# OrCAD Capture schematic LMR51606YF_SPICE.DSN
size D; title: LMR51606YF SIMPLE SWITCHERï¿½ 4.5-V to 65-V, 600-mA; note: Datasheet: SLUSEY1     EVM: SLUUCP7; note: Synchronous Step-Down Converter
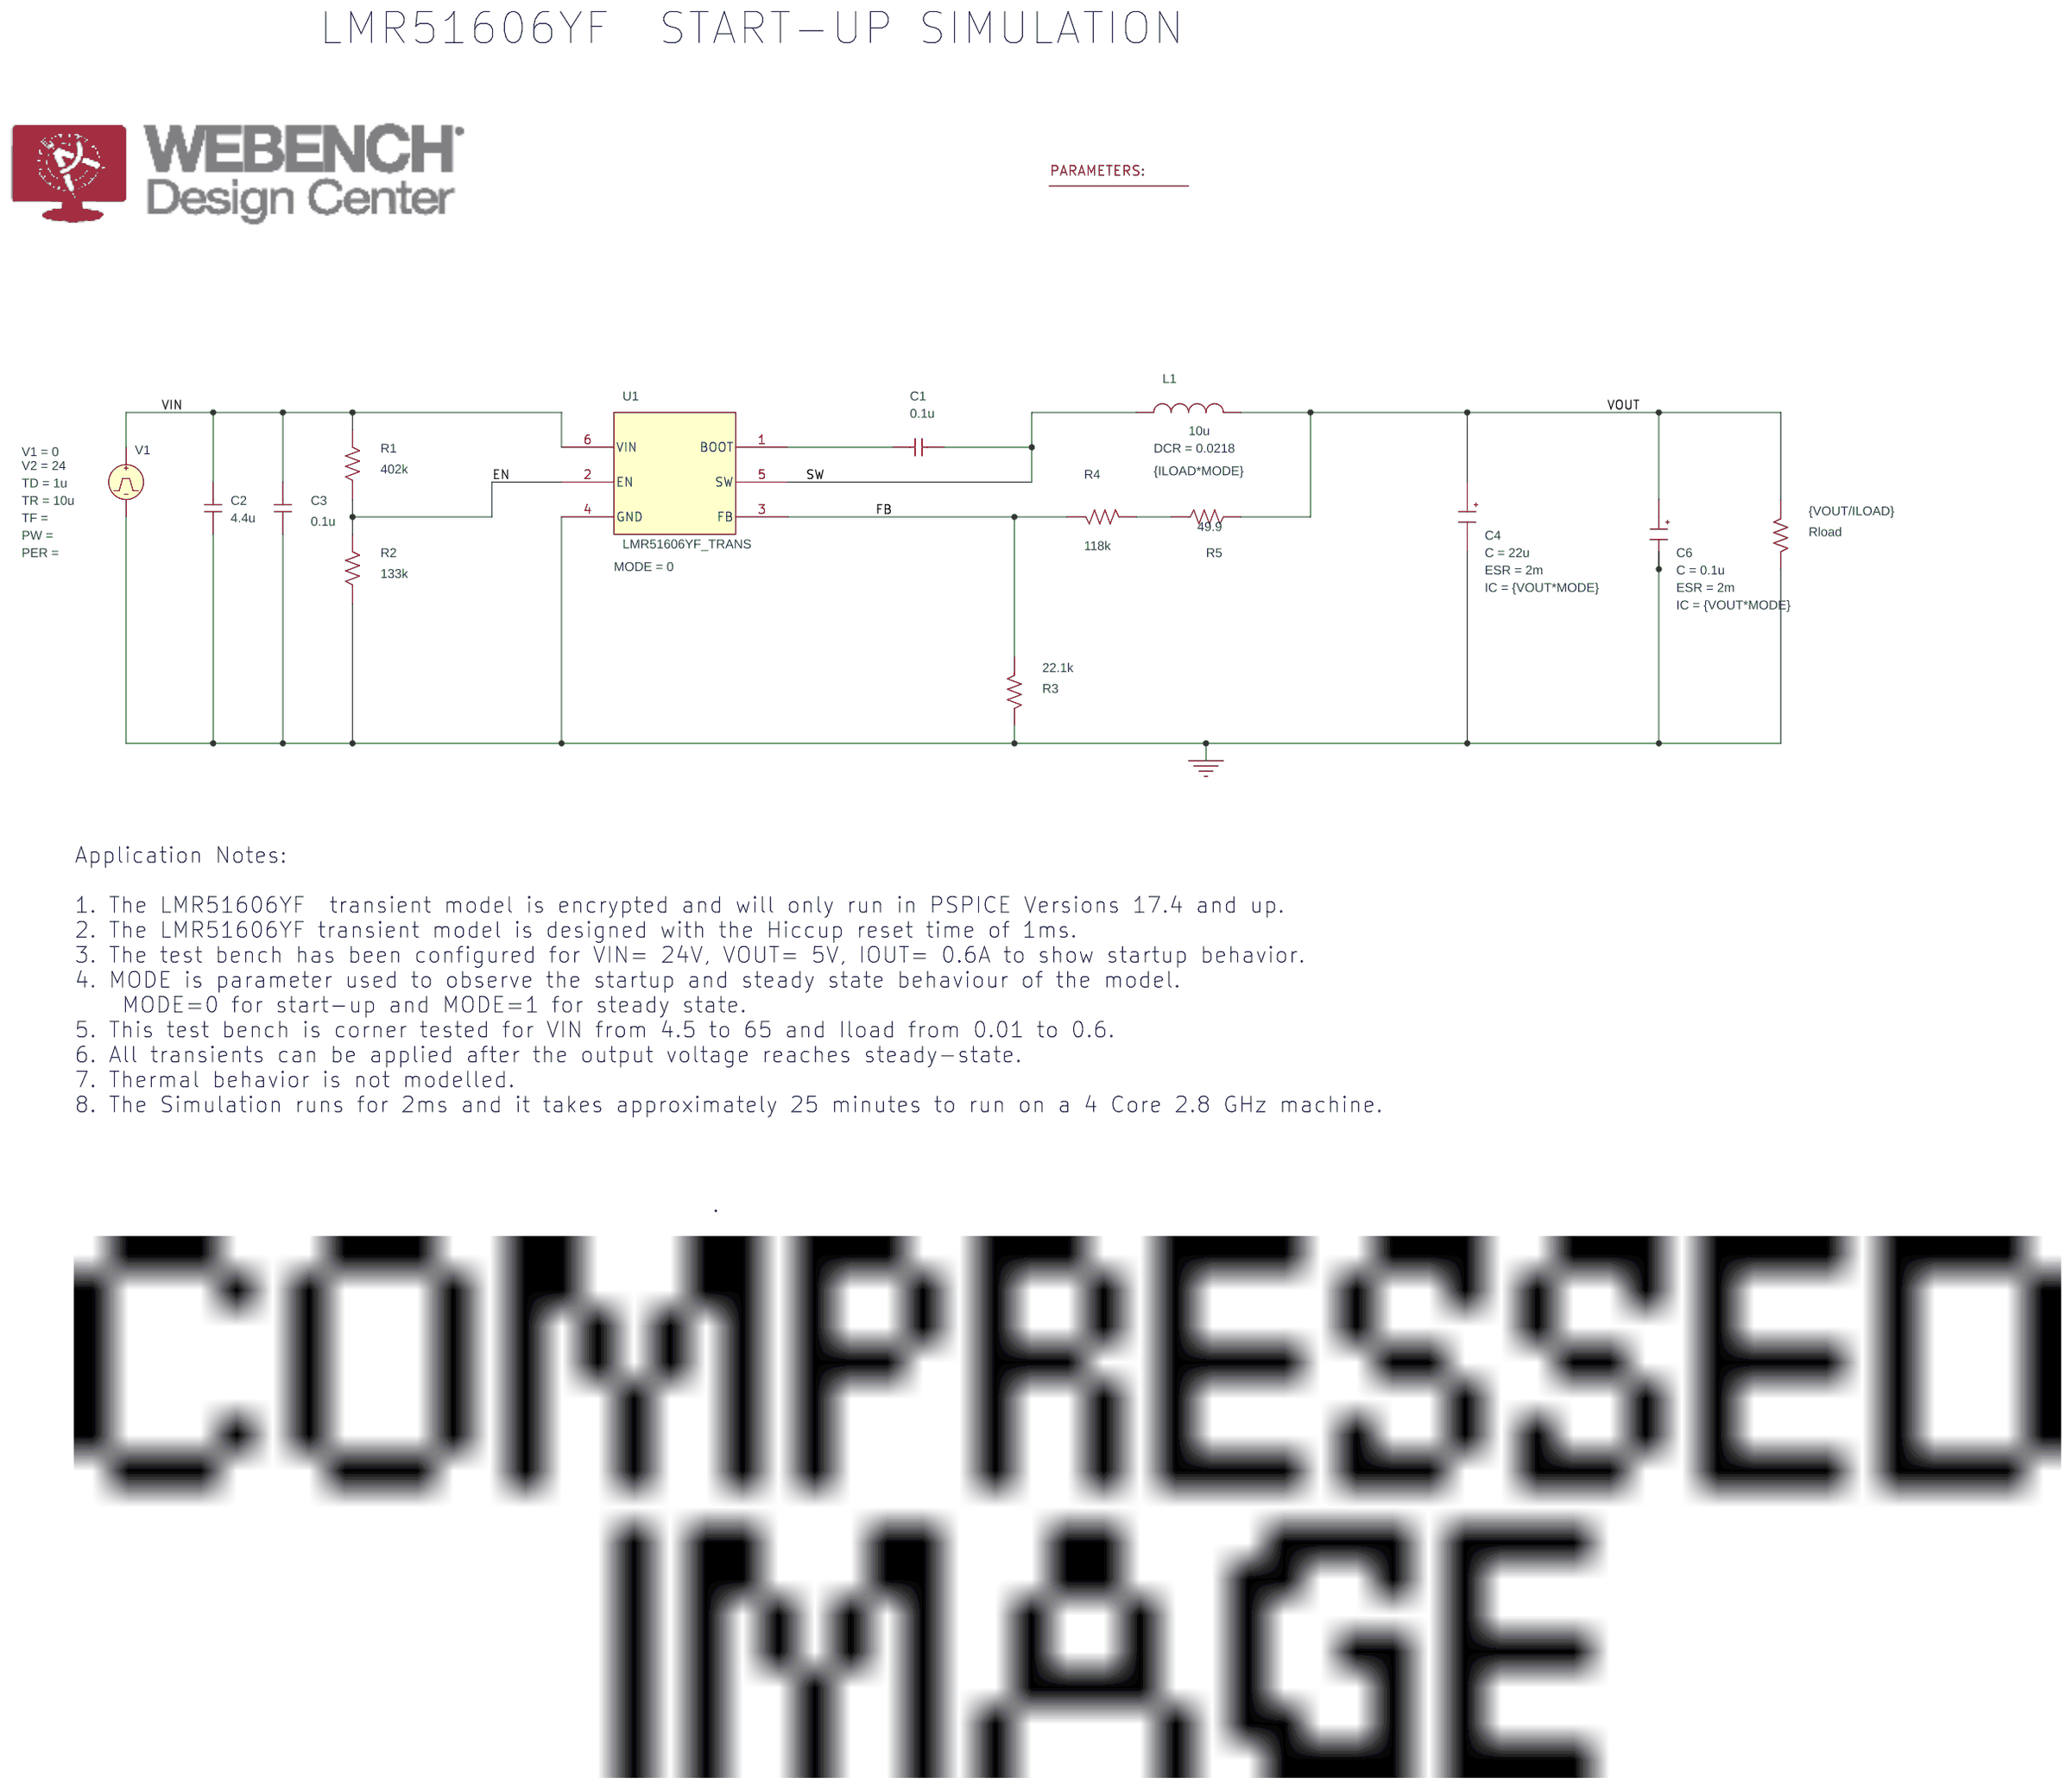
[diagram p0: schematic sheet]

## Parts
1  PARAM
C1  0.1u  [RAD/CK05]
C2  4.4u  [RAD/CK05]
C3  0.1u  [RAD/CK05]
C4  CESR
C6  CESR
L1  10u  [DISC/.350x.175/LS.200x.100/.034]
R1  402k  [AX/RC05]
R2  133k  [AX/RC05]
R3  22.1k  [AX/RC05]
R4  118k  [AX/RC05]
R5  49.9  [AX/RC05]
Rload  {VOUT/ILOAD}  [AX/RC05]
U1  LMR51606YF_TRANS
V1  VPULSE

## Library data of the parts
1 = PARAM: ILOAD: 0.1; MODE: 0; VOUT: 5
C1 = C: IC: -3.3
C2 C3 = C
C4 = CESR_0: C: 22u; ESR: 2m; IC: {VOUT*MODE}; PSpiceTemplate: X^@REFDES %IN %OUT @MODEL PARAMS:  ?C|C=@C||C=100u|  ?ESR|ESR=@ESR||ESR=0.01| ?X|X=@X||X=2|  ?IC|IC=@IC||IC=2|; X: 1
C6 = CESR_0: C: 0.1u; ESR: 2m; IC: {VOUT*MODE}; PSpiceTemplate: X^@REFDES %IN %OUT @MODEL PARAMS:  ?C|C=@C||C=100u|  ?ESR|ESR=@ESR||ESR=0.01| ?X|X=@X||X=2|  ?IC|IC=@IC||IC=2|; X: 1
L1 = L: DCR: 0.0218; IC: {ILOAD*MODE}
R1 R2 R5 Rload = R
R3 R4 = r
U1 = LMR51606YF_TRANS: MODE: 0; PSpiceTemplate: X^@REFDES  %BOOT %EN %FB %GND %SW %VIN @MODEL
V1 = VPULSE: TD: 1u; TR: 10u; V1: 0; V2: 24

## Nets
VIN: C2.2 C3.2 R1.2 U1.6(VIN) V1.1(+)
0: C2.1 C3.1 C4.3(OUT) C6.3(OUT) R2.1 R3.2 Rload.2 U1.4(GND) V1.2(-)
EN: R1.1 R2.2 U1.2(EN)
FB: R3.1 R4.1 U1.3(FB)
SW: C1.2 L1.1 U1.5(SW)
VOUT: C4.1(IN) C6.1(IN) L1.2 R5.2 Rload.1
N16764843: R4.2 R5.1
N16777902: C1.1 U1.1(BOOT)

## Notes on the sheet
- LMR51606YF  START-UP SIMULATION
- Application Notes:
  1. The LMR51606YF  transient model is encrypted and will only run in PSPICE Versions 17.4 and up.
  2. The LMR51606YF transient model is designed with the Hiccup reset time of 1ms.
  3. The test bench has been configured for VIN= 24V, VOUT= 5V, IOUT= 0.6A to show startup behavior.
  4. MODE is parameter used to observe the startup and steady state behaviour of the model.
      MODE=0 for start-up and MODE=1 for steady state.
  5. This test bench is corner tested for VIN from 4.5 to 65 and Iload from 0.01 to 0.6.
  6. All transients can be applied after the output voltage reaches steady-state.
  7. Thermal behavior is not modelled.
  8. The Simulation runs for 2ms and it takes approximately 25 minutes to run on a 4 Core 2.8 GHz machine.
                                                        .
